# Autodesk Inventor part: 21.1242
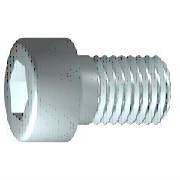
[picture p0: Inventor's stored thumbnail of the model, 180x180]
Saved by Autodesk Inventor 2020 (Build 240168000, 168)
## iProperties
Created: 2006-02
Part Number: 21.1242
Material: Steel, Mild
Description: M6X25 SHCS
Document SubType Name: Modeling
Standard: DIN 7984
Designer: Andy Moles
Standards Organization: DIN
Language: en-US
Size Designation: M6 x 25
Categories: <MemberInstance><Categories><Category DisplayName="Fasteners" InternalName="e4da775c-781d-43d5-af7c-5136215cf5a6" Mnemonic="FSTN"><Category DisplayName="Bolts"
Density: 7.85 g/cm^3
Mass: 7.58733 g
Surface Area: 7.83808 cm^2
Volume: 0.966539 cm^3
Vendor: S
Appearance: Zinc
Author: Andy Moles
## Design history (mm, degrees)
sketch "Sketch1"
  geometry: L1 (0.333, 0)-(25, 0); L2 (25, 0)-(25, 3); L3 (25, 3)-(3, 3); L4 (3, 3)-(2.386, 3); L5 (2.386, 3)-(0, 3); L6 (0, 3)-(0, 5); L7 (0, 5)-(-4, 5); L8 (-4, 5)-(-4, 2.309); L9 (-4, 2.309)-(-1, 2.309); L10 (-1, 2.309)-(0.333, 0); L11 (-6.9, 0)-(33.7, 0) reference; L12 (0, -0.5)-(0, 6.5) reference; L13 (3, 3)-(0, 3)
  constraints: 22 end point, 6 parallel, 2 collinear, 2 perpendicular, 1 horizontal, 1 midpoint
  dimensions: "d1" = 22 distance from line of L3.end L2 (= GEL); "d2" = 0.61355 distance of L4.end L3.end (computed from GAL); "d3" = 4 distance between parallel lines of L8 L6 (= KOH); "d4" = 3 distance of L8.end L9.end (= INTI); "d5" = 60 deg angle of L10 L1; "d6" = 6 diameter of L3 L1 (= GD); "d7" = 6 diameter of L5 L1 (= BDM); "d8" = 4.6188 diameter of L9 L1 (= 1.1547 x SW); "d9" = 10 diameter of L7 L1 (= KOD); "d26" = 25 distance between parallel lines of L12 L2 (= NLG)
revolve "Body" sketch "Sketch1" stored, may be unused: angle "d10" = 90 deg
sketch "Sketch2"
  geometry: L1 (0, -6)-(0, 8) reference; L2 (-6, 0)-(8, 0) reference; L3 (2.309, 0)-(1.155, -2); L4 (1.155, -2)-(-1.155, -2); L5 (-1.155, -2)-(-2.309, 0); L6 (-2.309, 0)-(-1.155, 2); L7 (-1.155, 2)-(1.155, 2); L8 (1.155, 2)-(2.309, 0); 2 further points
  constraints: 12 end point, 1 coincident, 1 horizontal alignment, 1 point on line, 12 other
extrude "Slot" join sketch "Sketch2" stored distance "d11" = 10; taper "d12" = 0 deg
workplane "Work Plane1"
body "Solid1"
fillet "Fillet1" dims "d17" = 0.6 (= RR)
feature "Thread" dims "d13" = 25, "d14" = 0
chamfer "Chamfer1" distance "d15" = 0.61345 (= -0.5 x SPD + 0.5 x GD); stored, may be unused: second distance "d16" = 0.61345 (= GUL), angle "d27" = 45 deg
other parameters: "GD" = 6 (= NND) [user parameter; used in 2 equation terms], "NLG" = 25 [user parameter; used in 1 equation term], "GEL" = 22 [user parameter; used in 1 equation term], "KOD" = 10 [user parameter; used in 1 equation term], "KOH" = 4 [user parameter; used in 1 equation term], "INTI" = 3 [user parameter; used in 1 equation term], "GAL" = 0.61345 (= 0.61345 x PTC) [user parameter; used in 1 equation term], "GUL" = 0.61345 (= 0.61345 x PTC) [user parameter; used in 1 equation term], "BDM" = 6 (= NND) [user parameter; used in 1 equation term], "SW" = 4 [user parameter; used in 2 equation terms], "RR" = 0.6 [user parameter; used in 1 equation term], "SPD" = 4.7731 (= NND - 1.2269 x PTC) [user parameter; used in 1 equation term], "d19" = 0, "d28" = 0, "d29" = 0, "TOA" = 30 deg [user parameter], "GD1" = 4.7731 (= THREADDIA - 1.2269 x PTC) [user parameter], "THREADDIA" = 6 [user parameter; used in 1 equation term], "FAWI" = 45 deg [user parameter], "ANG" = 120 deg [user parameter], "PTC" = 1 [user parameter; used in 5 equation terms], "NND" = 6 [user parameter; used in 3 equation terms], "E0" = 4.62 (= 1.155 x SW) [user parameter]
